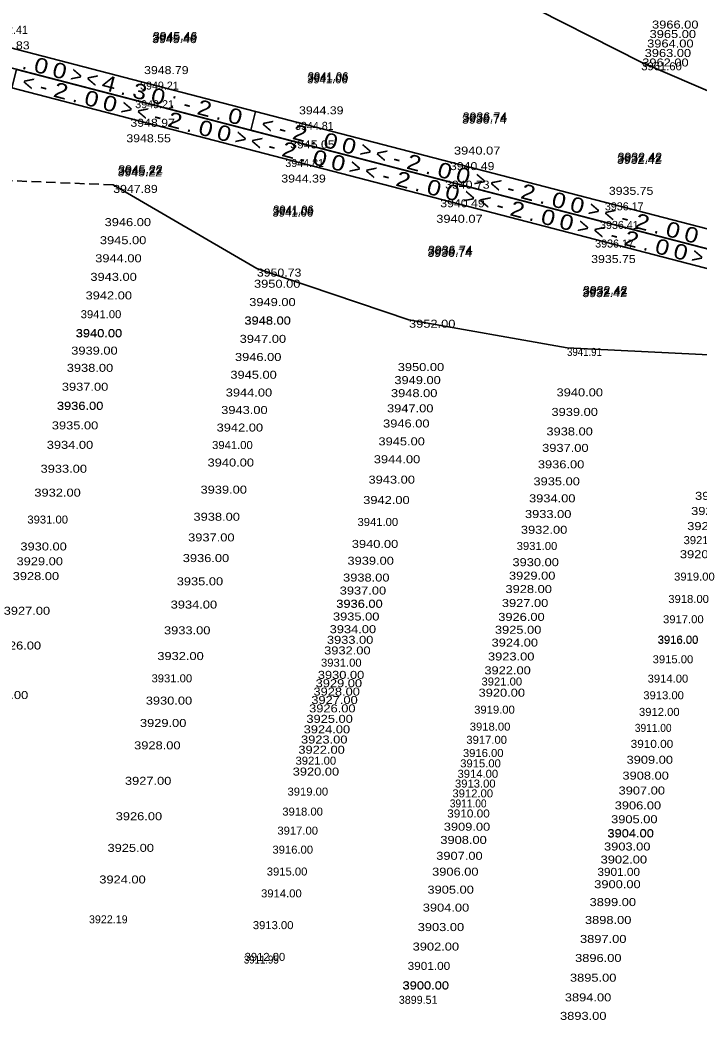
# Model space of a CAD drawing. Extents: x 49942 to 56479, y 47140 to 53283.
# Drawn here: x 54509 to 54933, y 49139 to 49763 of the extents above; entities that cross this region are included whole.
import ezdxf
from ezdxf.enums import TextEntityAlignment as Align

# ---------------------------------------------------------------- set-up
doc = ezdxf.new("R2010")
doc.units = 0
doc.header["$LTSCALE"] = 2
doc.linetypes.add('MEDIUM_DASHED', pattern=[4.5, 3, -1.5])
doc.layers.add('29', color=7, linetype='Continuous')
doc.layers.add('59', color=7, linetype='Continuous', lineweight=35)
doc.layers.add('63', color=7, linetype='Continuous', lineweight=35)

msp = doc.modelspace()

# ---------------------------------------------------------------- linework, layer by layer
at = {"layer": '59'}
for p, q in [((54896.947, 49736.929), (54805.688, 49783.359)), ((54989.852, 49696.838), (54896.947, 49736.929)), ((54656.848, 49608.089), (54567.105, 49660.354)), ((54751.855, 49576.093), (54656.848, 49608.089)), ((54850.61, 49558.526), (54751.855, 49576.093)), ((54952.657, 49553.632), (54850.61, 49558.526))]:
    msp.add_line(p, q, dxfattribs=at)
at = {"layer": '59', "linetype": 'MEDIUM_DASHED'}
msp.add_line((54567.105, 49660.354), (54464.871, 49664.531), dxfattribs=at)
at = {"layer": '63'}
msp.add_lwpolyline([(54471.664, 49754.021), (54656.01, 49706.141), (54652.993, 49694.526), (54468.647, 49742.406)], dxfattribs=at)
for points in [[(54503.671, 49720.911), (56472.661, 49209.506), (56475.677, 49221.12), (54506.687, 49732.526)], [(54656.01, 49706.141), (56478.694, 49232.735), (56475.677, 49221.12), (54652.993, 49694.526)]]:
    msp.add_lwpolyline(points, close=True, dxfattribs=at)

# ---------------------------------------------------------------- texts
at = {"layer": '29'}
for s, width, p in [('3966.00', 1.2, (54903.715, 49757.986)), ('3965.00', 1.2, (54902.179, 49752.073)), ('3945.46', 1.15, (54591.405, 49748.915)), ('3945.46', 1.15, (54591.657, 49749.883)), ('3945.46', 1.15, (54591.908, 49750.851)), ('3964.00', 1.2, (54900.643, 49746.16)), ('3952.83', 1.15, (54487.075, 49745.018)), ('3963.00', 1.2, (54899.104, 49740.234)), ('3962.00', 1.2, (54897.565, 49734.308)), ('3948.79', 1.15, (54586.377, 49729.558)), ('3961.60', 1.05, (54896.947, 49731.929)), ('3941.06', 1.05, (54688.194, 49723.777)), ('3941.06', 1.05, (54688.445, 49724.745)), ('3941.06', 1.05, (54688.697, 49725.712)), ('3944.39', 1.15, (54683.166, 49704.419)), ('3948.97', 1.15, (54577.83, 49696.65)), ('3936.74', 1.15, (54784.982, 49698.638)), ('3936.74', 1.15, (54785.234, 49699.606)), ('3936.74', 1.15, (54785.485, 49700.574)), ('3948.55', 1.15, (54575.316, 49686.971)), ('3945.05', 1.15, (54677.635, 49683.126)), ('3940.07', 1.2, (54779.955, 49679.28)), ('3932.42', 1.15, (54881.771, 49673.499)), ('3932.42', 1.15, (54882.022, 49674.467)), ('3932.42', 1.15, (54882.274, 49675.435)), ('3945.22', 1.15, (54569.786, 49665.677)), ('3945.22', 1.15, (54570.037, 49666.645)), ('3945.22', 1.15, (54570.289, 49667.613)), ('3940.49', 1.15, (54777.441, 49669.601)), ('3944.39', 1.15, (54672.105, 49661.832)), ('3940.73', 1.15, (54774.424, 49657.987)), ('3947.89', 1.15, (54567.105, 49655.354)), ('3935.75', 1.15, (54876.743, 49654.141)), ('3940.49', 1.15, (54771.407, 49646.372)), ('3941.06', 1.05, (54666.574, 49640.538)), ('3941.06', 1.05, (54666.826, 49641.506)), ('3941.06', 1.05, (54667.077, 49642.474)), ('3946.00', 1.2, (54561.718, 49634.613)), ('3940.07', 1.2, (54768.893, 49636.693)), ('3945.00', 1.2, (54558.783, 49623.313)), ('3936.74', 1.15, (54763.363, 49615.4)), ('3936.74', 1.15, (54763.614, 49616.367)), ('3936.74', 1.15, (54763.866, 49617.335)), ('3944.00', 1.2, (54555.848, 49612.014)), ('3935.75', 1.15, (54865.682, 49611.554)), ('3950.73', 1.15, (54656.848, 49603.089)), ('3943.00', 1.2, (54552.837, 49600.422)), ('3950.00', 1.2, (54655.038, 49596.122)), ('3932.42', 1.15, (54860.152, 49590.261)), ('3932.42', 1.15, (54860.403, 49591.229)), ('3932.42', 1.15, (54860.654, 49592.196)), ('3942.00', 1.2, (54549.827, 49588.831)), ('3949.00', 1.2, (54652.064, 49584.673)), ('3941.00', 1.05, (54546.78, 49577.102)), ('3948.00', 1.2, (54649.044, 49573.045)), ('3948.00', 1.2, (54649.068, 49573.138)), ('3948.00', 1.2, (54649.091, 49573.224)), ('3952.00', 1.2, (54751.869, 49571.144)), ('3940.00', 1.2, (54543.666, 49565.112)), ('3940.00', 1.2, (54543.704, 49565.261)), ('3940.00', 1.2, (54543.734, 49565.374)), ('3947.00', 1.2, (54646.1, 49561.71)), ('3939.00', 1.2, (54540.873, 49554.357)), ('3941.91', 0.9, (54850.61, 49553.526)), ('3946.00', 1.2, (54643.156, 49550.374)), ('3938.00', 1.2, (54538.079, 49543.603)), ('3945.00', 1.2, (54640.276, 49539.284)), ('3950.00', 1.2, (54744.842, 49544.089)), ('3949.00', 1.2, (54742.726, 49535.945)), ('3937.00', 1.2, (54535.011, 49531.79)), ('3944.00', 1.2, (54637.395, 49528.194)), ('3948.00', 1.2, (54740.611, 49527.8)), ('3940.00', 1.2, (54844.051, 49528.271)), ('3936.00', 1.2, (54531.896, 49519.795)), ('3936.00', 1.2, (54531.919, 49519.886)), ('3936.00', 1.2, (54531.943, 49519.977)), ('3943.00', 1.2, (54634.553, 49517.251)), ('3947.00', 1.2, (54738.15, 49518.324)), ('3939.00', 1.2, (54840.884, 49516.077)), ('3946.00', 1.2, (54735.688, 49508.848)), ('3935.00', 1.2, (54528.741, 49507.651)), ('3942.00', 1.2, (54631.711, 49506.309)), ('3938.00', 1.2, (54837.717, 49503.883)), ('3934.00', 1.2, (54525.587, 49495.506)), ('3941.00', 1.05, (54628.875, 49495.391)), ('3945.00', 1.2, (54732.788, 49497.68)), ('3937.00', 1.2, (54835.049, 49493.61)), ('3940.00', 1.2, (54626.039, 49484.473)), ('3944.00', 1.2, (54729.887, 49486.512)), ('3936.00', 1.2, (54832.381, 49483.338)), ('3933.00', 1.2, (54521.713, 49480.588)), ('3943.00', 1.2, (54726.58, 49473.78)), ('3935.00', 1.2, (54829.622, 49472.718)), ('3932.00', 1.2, (54517.838, 49465.67)), ('3939.00', 1.2, (54621.641, 49467.538)), ('3942.00', 1.2, (54723.273, 49461.047)), ('3934.00', 1.2, (54826.864, 49462.099)), ('3924.00', 1.2, (54930.587, 49463.659)), ('3933.00', 1.2, (54824.315, 49452.285)), ('3923.00', 1.2, (54928.134, 49454.213)), ('3931.00', 1.05, (54513.471, 49448.857)), ('3938.00', 1.2, (54617.243, 49450.604)), ('3941.00', 1.05, (54719.714, 49447.343)), ('3932.00', 1.2, (54821.767, 49442.472)), ('3922.00', 1.2, (54925.681, 49444.767)), ('3937.00', 1.2, (54613.89, 49437.697)), ('3940.00', 1.2, (54716.154, 49433.638)), ('3921.00', 1.05, (54923.403, 49435.996)), ('3930.00', 1.2, (54509.104, 49432.044)), ('3931.00', 1.05, (54819.137, 49432.349)), ('3920.00', 1.2, (54921.118, 49427.202)), ('3929.00', 1.2, (54506.7, 49422.789)), ('3936.00', 1.2, (54610.538, 49424.79)), ('3939.00', 1.2, (54713.425, 49423.132)), ('3930.00', 1.2, (54816.508, 49422.226)), ('3928.00', 1.2, (54504.296, 49413.533)), ('3935.00', 1.2, (54606.767, 49410.272)), ('3938.00', 1.2, (54710.696, 49412.626)), ('3929.00', 1.2, (54814.328, 49413.832)), ('3919.00', 1.05, (54917.489, 49413.23)), ('3937.00', 1.2, (54708.59, 49404.514)), ('3928.00', 1.2, (54812.147, 49405.437)), ('3934.00', 1.2, (54602.997, 49395.754)), ('3936.00', 1.2, (54706.431, 49396.204)), ('3936.00', 1.2, (54706.448, 49396.268)), ('3936.00', 1.2, (54706.464, 49396.331)), ('3927.00', 1.2, (54809.89, 49396.745)), ('3918.00', 1.05, (54913.861, 49399.259)), ('3927.00', 1.2, (54498.675, 49391.889)), ('3935.00', 1.2, (54704.377, 49388.293)), ('3926.00', 1.2, (54807.632, 49388.052)), ('3917.00', 1.05, (54910.571, 49386.592)), ('3933.00', 1.2, (54598.821, 49379.677)), ('3934.00', 1.2, (54702.322, 49380.381)), ('3925.00', 1.2, (54805.549, 49380.034)), ('3933.00', 1.2, (54700.598, 49373.746)), ('3924.00', 1.2, (54803.467, 49372.016)), ('3916.00', 1.05, (54907.211, 49373.656)), ('3916.00', 1.05, (54907.249, 49373.805)), ('3916.00', 1.05, (54907.281, 49373.926)), ('3926.00', 1.2, (54493.034, 49370.171)), ('3932.00', 1.2, (54698.875, 49367.112)), ('3932.00', 1.2, (54594.645, 49363.601)), ('3931.00', 1.05, (54696.895, 49359.487)), ('3923.00', 1.2, (54801.216, 49363.349)), ('3915.00', 1.05, (54904.075, 49361.583)), ('3930.00', 1.2, (54694.914, 49351.861)), ('3922.00', 1.2, (54798.965, 49354.682)), ('3931.00', 1.05, (54591.032, 49349.689)), ('3929.00', 1.2, (54693.556, 49346.632)), ('3921.00', 1.05, (54797.152, 49347.702)), ('3914.00', 1.05, (54900.94, 49349.51)), ('3925.00', 1.2, (54485.001, 49339.244)), ('3928.00', 1.2, (54692.198, 49341.403)), ('3920.00', 1.2, (54795.339, 49340.722)), ('3930.00', 1.2, (54587.419, 49335.777)), ('3927.00', 1.2, (54690.837, 49336.164)), ('3913.00', 1.05, (54898.241, 49339.123)), ('3926.00', 1.2, (54689.476, 49330.924)), ('3919.00', 1.05, (54792.588, 49330.132)), ('3912.00', 1.05, (54895.544, 49328.735)), ('3929.00', 1.2, (54583.79, 49321.807)), ('3925.00', 1.2, (54687.778, 49324.386)), ('3924.00', 1.2, (54686.08, 49317.848)), ('3918.00', 1.05, (54789.838, 49319.541)), ('3911.00', 0.95, (54892.95, 49318.749)), ('3923.00', 1.2, (54684.424, 49311.471)), ('3917.00', 1.05, (54787.697, 49311.301)), ('3910.00', 1.1, (54890.356, 49308.762)), ('3928.00', 1.2, (54580.162, 49307.838)), ('3922.00', 1.2, (54682.767, 49305.094)), ('3916.00', 1.05, (54785.557, 49303.06)), ('3921.00', 1.05, (54680.996, 49298.275)), ('3915.00', 1.05, (54783.873, 49296.575)), ('3909.00', 1.2, (54887.781, 49298.847)), ('3920.00', 1.2, (54679.225, 49291.456)), ('3914.00', 1.05, (54782.188, 49290.089)), ('3927.00', 1.2, (54574.411, 49285.696)), ('3913.00', 1.05, (54780.597, 49283.961)), ('3908.00', 1.2, (54885.206, 49288.932)), ('3919.00', 1.05, (54675.98, 49278.961)), ('3912.00', 1.05, (54779.005, 49277.834)), ('3907.00', 1.2, (54882.79, 49279.63)), ('3911.00', 0.95, (54777.376, 49271.56)), ('3918.00', 1.05, (54672.734, 49266.465)), ('3910.00', 1.1, (54775.746, 49265.287)), ('3906.00', 1.2, (54880.373, 49270.328)), ('3926.00', 1.2, (54568.66, 49263.554)), ('3905.00', 1.2, (54878.129, 49261.686)), ('3917.00', 1.05, (54669.647, 49254.58)), ('3909.00', 1.2, (54773.601, 49257.027)), ('3904.00', 1.2, (54875.818, 49252.789)), ('3904.00', 1.2, (54875.852, 49252.92)), ('3904.00', 1.2, (54875.885, 49253.045)), ('3908.00', 1.2, (54771.456, 49248.768)), ('3925.00', 1.2, (54563.532, 49243.81)), ('3916.00', 1.05, (54666.56, 49242.695)), ('3903.00', 1.2, (54873.704, 49244.652)), ('3907.00', 1.2, (54768.88, 49238.852)), ('3902.00', 1.2, (54871.591, 49236.515)), ('3915.00', 1.05, (54663.013, 49229.036)), ('3906.00', 1.2, (54766.305, 49228.936)), ('3901.00', 1.1, (54869.59, 49228.809)), ('3924.00', 1.2, (54558.404, 49224.066)), ('3900.00', 1.2, (54867.588, 49221.103)), ('3914.00', 1.05, (54659.465, 49215.378)), ('3905.00', 1.2, (54763.392, 49217.72)), ('3899.00', 1.2, (54864.69, 49209.944)), ('3904.00', 1.2, (54760.479, 49206.504)), ('3898.00', 1.2, (54861.791, 49198.785)), ('3913.00', 1.05, (54654.316, 49195.552)), ('3903.00', 1.2, (54757.318, 49194.337)), ('3897.00', 1.2, (54858.713, 49186.932)), ('3902.00', 1.2, (54754.158, 49182.17)), ('3911.95', 0.9, (54648.73, 49174.044)), ('3912.00', 1.05, (54649.167, 49175.727)), ('3896.00', 1.2, (54855.628, 49175.053)), ('3901.00', 1.1, (54751.023, 49170.097)), ('3895.00', 1.2, (54852.43, 49162.741)), ('3900.00', 1.2, (54747.829, 49157.801)), ('3900.00', 1.2, (54747.861, 49157.923)), ('3900.00', 1.2, (54747.887, 49158.025)), ('3894.00', 1.2, (54849.232, 49150.429)), ('3893.00', 1.2, (54846.232, 49138.878))]:
    msp.add_text(s, height=5, dxfattribs=dict(at, width=width)).set_placement(p)
for s, p in [('3952.41', (54489.589, 49754.697)), ('3949.21', (54583.863, 49719.879)), ('3949.21', (54580.847, 49708.264)), ('3944.81', (54680.652, 49694.74)), ('3944.81', (54674.619, 49671.511)), ('3936.17', (54874.229, 49644.462)), ('3936.41', (54871.213, 49632.848)), ('3936.17', (54868.196, 49621.233)), ('3922.19', (54551.941, 49199.183)), ('3899.51', (54745.518, 49148.905))]:
    msp.add_text(s, height=5, dxfattribs=at).set_placement(p)
at = {"layer": '63'}
for s, width, p in [('0', 1.2, (54520.997, 49730.049)), ('0', 1.2, (54532.459, 49727.072)), ('>', 0.95, (54543.052, 49724.321)), ('<', 0.95, (54512.945, 49719.742)), ('<', 0.95, (54552.777, 49721.795)), ('4', 1.2, (54563.37, 49719.043)), ('-', 1.1, (54522.67, 49717.216)), ('2', 1.2, (54533.263, 49714.465)), ('0', 1.2, (54552.468, 49709.477)), ('3', 1.2, (54582.576, 49714.055)), ('0', 1.2, (54594.038, 49711.078)), ('0', 1.2, (54563.931, 49706.5)), ('2', 1.2, (54622.968, 49703.564)), ('>', 0.95, (54574.524, 49703.748)), ('<', 0.95, (54584.249, 49701.223)), ('-', 1.1, (54612.374, 49706.316)), ('0', 1.2, (54642.173, 49698.576)), ('-', 1.1, (54593.973, 49698.697)), ('2', 1.2, (54604.566, 49695.945)), ('0', 1.2, (54623.772, 49690.957)), ('<', 0.95, (54662.267, 49693.357)), ('0', 1.2, (54635.234, 49687.98)), ('-', 1.1, (54671.992, 49690.831)), ('2', 1.2, (54682.585, 49688.08)), ('>', 0.95, (54645.827, 49685.229)), ('<', 0.95, (54655.552, 49682.703)), ('0', 1.2, (54701.791, 49683.092)), ('0', 1.2, (54713.253, 49680.114)), ('-', 1.1, (54665.277, 49680.177)), ('2', 1.2, (54675.87, 49677.426)), ('0', 1.2, (54695.075, 49672.438)), ('>', 0.95, (54723.846, 49677.363)), ('<', 0.95, (54733.571, 49674.837)), ('0', 1.2, (54706.537, 49669.46)), ('>', 0.95, (54717.131, 49666.709)), ('-', 1.1, (54743.295, 49672.312)), ('2', 1.2, (54753.889, 49669.56)), ('<', 0.95, (54726.856, 49664.183)), ('0', 1.2, (54773.094, 49664.572)), ('0', 1.2, (54784.556, 49661.595)), ('-', 1.1, (54736.58, 49661.658)), ('2', 1.2, (54747.173, 49658.906)), ('0', 1.2, (54766.379, 49653.918)), ('>', 0.95, (54795.15, 49658.843)), ('<', 0.95, (54804.874, 49656.318)), ('0', 1.2, (54777.841, 49650.941)), ('>', 0.95, (54788.434, 49648.19)), ('-', 1.1, (54814.599, 49653.792)), ('2', 1.2, (54825.192, 49651.04)), ('<', 0.95, (54798.159, 49645.664)), ('0', 1.2, (54844.398, 49646.052)), ('0', 1.2, (54855.86, 49643.075)), ('-', 1.1, (54807.884, 49643.138)), ('2', 1.2, (54818.477, 49640.386)), ('0', 1.2, (54837.682, 49635.398)), ('>', 0.95, (54866.453, 49640.324)), ('<', 0.95, (54876.178, 49637.798)), ('0', 1.2, (54849.144, 49632.421)), ('>', 0.95, (54859.738, 49629.67)), ('-', 1.1, (54885.902, 49635.272)), ('2', 1.2, (54896.496, 49632.521)), ('<', 0.95, (54869.463, 49627.144)), ('2', 1.2, (54889.78, 49621.867)), ('0', 1.2, (54915.701, 49627.533)), ('0', 1.2, (54927.163, 49624.556)), ('-', 1.1, (54879.187, 49624.618)), ('0', 1.2, (54908.986, 49616.879)), ('0', 1.2, (54920.448, 49613.902)), ('>', 0.95, (54931.041, 49611.15))]:
    msp.add_text(s, height=9.6, rotation=345.44, dxfattribs=dict(at, width=width)).set_placement(p, align=Align.CENTER)
for s, p in [('.', (54511.394, 49732.543)), ('.', (54542.866, 49711.971)), ('.', (54572.973, 49716.549)), (':', (54603.64, 49708.584)), ('.', (54632.57, 49701.07)), ('.', (54614.169, 49693.451)), ('.', (54692.188, 49685.586)), ('.', (54685.473, 49674.932)), ('.', (54763.491, 49667.066)), ('.', (54756.776, 49656.412)), ('.', (54834.795, 49648.546)), ('.', (54828.08, 49637.892)), ('.', (54906.098, 49630.027)), ('.', (54899.383, 49619.373))]:
    msp.add_text(s, height=9.6, rotation=345.44, dxfattribs=at).set_placement(p, align=Align.CENTER)

doc.saveas('drawing.dxf')
